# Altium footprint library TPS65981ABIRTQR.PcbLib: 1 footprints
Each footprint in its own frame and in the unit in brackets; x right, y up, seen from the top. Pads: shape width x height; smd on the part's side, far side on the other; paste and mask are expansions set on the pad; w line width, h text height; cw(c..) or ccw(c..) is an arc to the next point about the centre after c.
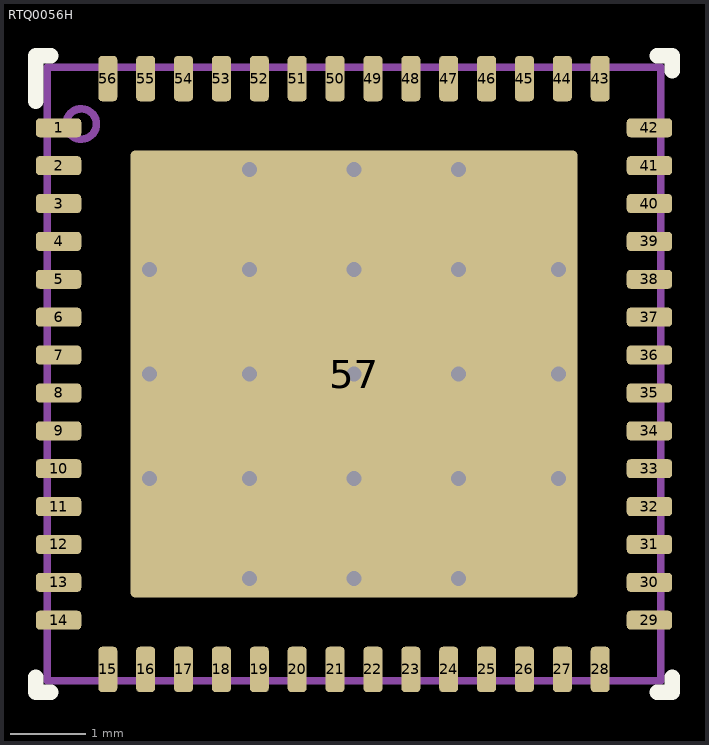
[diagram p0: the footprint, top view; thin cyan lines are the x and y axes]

## RTQ0056H [mm] "SMD, 56-Leads, Body 8x8mm, Pitch 0.5mm"
height 1
pads (73):
  rrect40% 0.6x0.25 smd paste+0: 1(-1124.802,-1221.538) 2(-1124.802,-1222.038) 3(-1124.802,-1222.538) 4(-1124.802,-1223.038) 5(-1124.802,-1223.538) 6(-1124.802,-1224.038) 7(-1124.802,-1224.538) 8(-1124.802,-1225.038) 9(-1124.802,-1225.538) 10(-1124.802,-1226.038) 11(-1124.802,-1226.538) 12(-1124.802,-1227.038) 13(-1124.802,-1227.538) 14(-1124.802,-1228.038) 29(-1117.002,-1228.038) 30(-1117.002,-1227.538) 31(-1117.002,-1227.038) 32(-1117.002,-1226.538) 33(-1117.002,-1226.038) 34(-1117.002,-1225.538) 35(-1117.002,-1225.038) 36(-1117.002,-1224.538) 37(-1117.002,-1224.038) 38(-1117.002,-1223.538) 39(-1117.002,-1223.038) 40(-1117.002,-1222.538) 41(-1117.002,-1222.038) 42(-1117.002,-1221.538)
  rrect40% 0.25x0.6 smd paste+0: 15(-1124.152,-1228.688) 16(-1123.652,-1228.688) 17(-1123.152,-1228.688) 18(-1122.652,-1228.688) 19(-1122.152,-1228.688) 20(-1121.652,-1228.688) 21(-1121.152,-1228.688) 22(-1120.652,-1228.688) 23(-1120.152,-1228.688) 24(-1119.652,-1228.688) 25(-1119.152,-1228.688) 26(-1118.652,-1228.688) 27(-1118.152,-1228.688) 28(-1117.652,-1228.688) 43(-1117.652,-1220.888) 44(-1118.152,-1220.888) 45(-1118.652,-1220.888) 46(-1119.152,-1220.888) 47(-1119.652,-1220.888) 48(-1120.152,-1220.888) 49(-1120.652,-1220.888) 50(-1121.152,-1220.888) 51(-1121.652,-1220.888) 52(-1122.152,-1220.888) 53(-1122.652,-1220.888) 54(-1123.152,-1220.888) 55(-1123.652,-1220.888) 56(-1124.152,-1220.888)
  rrect2% 5.9x5.9 smd paste-6: 57(-1120.902,-1224.788)
  rrect50% 1.18x1.18 on Top Paste: ""(-1122.972,-1226.858) ""(-1122.972,-1225.478) ""(-1122.972,-1224.098) ""(-1122.972,-1222.718) ""(-1121.592,-1226.858) ""(-1121.592,-1225.478) ""(-1121.592,-1224.098) ""(-1121.592,-1222.718) ""(-1120.212,-1226.858) ""(-1120.212,-1225.478) ""(-1120.212,-1224.098) ""(-1120.212,-1222.718) ""(-1118.832,-1226.858) ""(-1118.832,-1225.478) ""(-1118.832,-1224.098) ""(-1118.832,-1222.718)
via -1123.602,-1224.788 diameter 0.5 hole 0.2
via -1123.602,-1226.168 diameter 0.5 hole 0.2
via -1123.602,-1223.408 diameter 0.5 hole 0.2
via -1120.902,-1223.408 diameter 0.5 hole 0.2
via -1120.902,-1222.088 diameter 0.5 hole 0.2
via -1120.902,-1227.488 diameter 0.5 hole 0.2
via -1120.902,-1226.168 diameter 0.5 hole 0.2
via -1120.902,-1224.788 diameter 0.5 hole 0.2
via -1122.282,-1223.408 diameter 0.5 hole 0.2
via -1122.282,-1222.088 diameter 0.5 hole 0.2
via -1122.282,-1227.488 diameter 0.5 hole 0.2
via -1122.282,-1226.168 diameter 0.5 hole 0.2
via -1122.282,-1224.788 diameter 0.5 hole 0.2
via -1119.522,-1224.788 diameter 0.5 hole 0.2
via -1119.522,-1226.168 diameter 0.5 hole 0.2
via -1119.522,-1227.488 diameter 0.5 hole 0.2
via -1119.522,-1222.088 diameter 0.5 hole 0.2
via -1119.522,-1223.408 diameter 0.5 hole 0.2
via -1118.202,-1223.408 diameter 0.5 hole 0.2
via -1118.202,-1226.168 diameter 0.5 hole 0.2
via -1118.202,-1224.788 diameter 0.5 hole 0.2
Top Overlay:
  lines w0.2: -1125.102,-1228.788 -1125.102,-1228.988 -1124.902,-1228.988 ; -1125.102,-1221.188 -1125.102,-1220.588 -1124.902,-1220.588 ; -1116.902,-1228.988 -1116.702,-1228.988 -1116.702,-1228.788 ; -1116.902,-1220.588 -1116.702,-1220.588 -1116.702,-1220.788
Mechanical 5:
  circle w0.1: c-1124.502,-1221.488 r0.2
  lines w0.1: -1124.952,-1228.838 -1124.952,-1220.738 -1116.852,-1220.738 -1116.852,-1228.838 -1124.952,-1228.838
  text ".Designator" at -1122.426,-1225.296 h1.02
3D body: height 1, standoff 0, extent -1124.902,-1228.788 -1116.902,-1220.788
